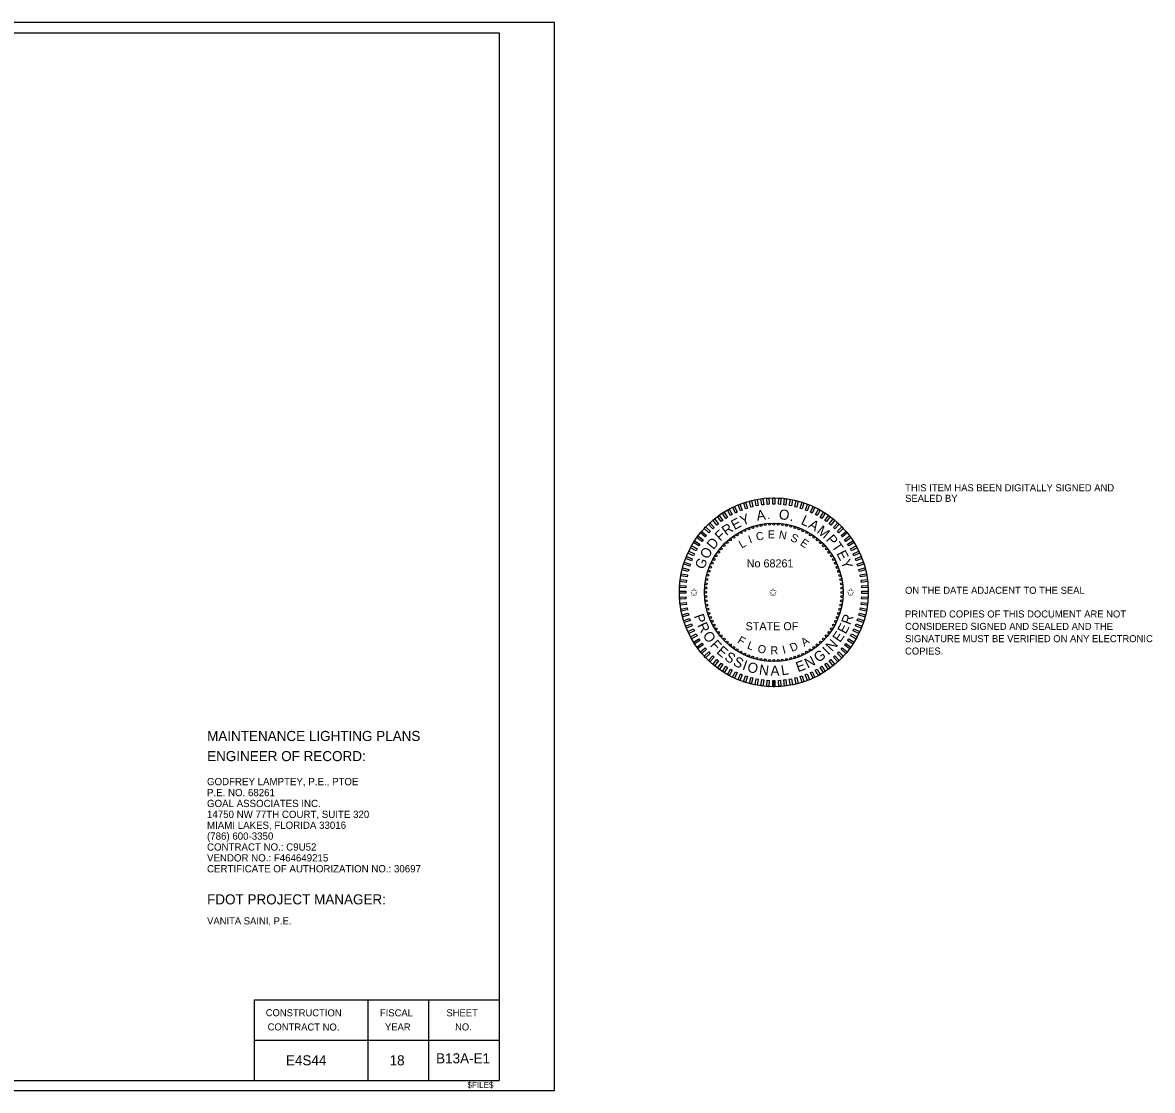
# Model space of a CAD drawing. Extents: x -828 to -798, y -2199 to -1895.
# Drawn here: x -809.01 to -797.79, y -2199.12 to -2188.52 of the extents above; entities that cross this region are included whole.
import ezdxf

# ---------------------------------------------------------------- set-up
doc = ezdxf.new("R2010")
doc.units = 0
for name, color, linetype in [('ActivePointCell_dp', 7, 'Continuous'), ('Logo_dp', 7, 'Continuous'), ('NonPlottingEle_dp', 7, 'Continuous'), ('PlotBorder_dp', 7, 'Continuous'), ('SheetBorder_dp', 7, 'Continuous'), ('SheetLines_dp', 7, 'Continuous'), ('TextLabel', 7, 'Continuous'), ('TextMinor', 7, 'Continuous'), ('TextMisc', 7, 'Continuous'), ('TextNotes', 7, 'Continuous')]:
    doc.layers.add(name, color=color, linetype=linetype)

msp = doc.modelspace()

# ---------------------------------------------------------------- linework, layer by layer
at = {"layer": 'ActivePointCell_dp'}
msp.add_line((-804.277, -2188.624), (-804.277, -2188.624), dxfattribs=at)
at = {"layer": 'Logo_dp'}
for p, q in [((-801.56, -2195.117), (-801.56, -2195.054)), ((-801.55, -2195.117), (-801.55, -2195.054)), ((-801.54, -2195.117), (-801.54, -2195.054))]:
    msp.add_line(p, q, dxfattribs=at)
for points in [[(-801.914, -2193.383), (-801.932, -2193.392), (-801.958, -2193.335), (-801.94, -2193.327)], [(-801.863, -2193.362), (-801.882, -2193.369), (-801.905, -2193.311), (-801.886, -2193.304)], [(-801.811, -2193.344), (-801.83, -2193.35), (-801.849, -2193.291), (-801.83, -2193.285)], [(-801.758, -2193.329), (-801.777, -2193.334), (-801.793, -2193.274), (-801.773, -2193.269)], [(-801.704, -2193.318), (-801.724, -2193.322), (-801.736, -2193.26), (-801.716, -2193.257)], [(-801.65, -2193.31), (-801.67, -2193.312), (-801.678, -2193.251), (-801.658, -2193.248)], [(-801.595, -2193.305), (-801.615, -2193.307), (-801.619, -2193.244), (-801.599, -2193.243)], [(-801.54, -2193.304), (-801.56, -2193.304), (-801.56, -2193.242), (-801.54, -2193.242)], [(-801.485, -2193.307), (-801.505, -2193.305), (-801.501, -2193.243), (-801.481, -2193.244)], [(-801.43, -2193.313), (-801.45, -2193.31), (-801.443, -2193.248), (-801.423, -2193.251)], [(-801.376, -2193.322), (-801.396, -2193.318), (-801.384, -2193.257), (-801.364, -2193.26)], [(-801.323, -2193.334), (-801.342, -2193.329), (-801.327, -2193.269), (-801.307, -2193.274)], [(-801.27, -2193.35), (-801.289, -2193.344), (-801.27, -2193.285), (-801.251, -2193.291)], [(-801.219, -2193.37), (-801.237, -2193.362), (-801.214, -2193.304), (-801.196, -2193.311)], [(-801.168, -2193.392), (-801.187, -2193.383), (-801.16, -2193.327), (-801.142, -2193.335)], [(-802.1, -2193.499), (-802.116, -2193.512), (-802.155, -2193.463), (-802.14, -2193.451)], [(-802.056, -2193.465), (-802.073, -2193.477), (-802.109, -2193.427), (-802.093, -2193.415)], [(-802.01, -2193.435), (-802.027, -2193.446), (-802.061, -2193.393), (-802.044, -2193.382)], [(-801.963, -2193.408), (-801.98, -2193.417), (-802.011, -2193.363), (-801.993, -2193.353)], [(-801.12, -2193.417), (-801.137, -2193.408), (-801.107, -2193.353), (-801.09, -2193.363)], [(-801.073, -2193.446), (-801.09, -2193.435), (-801.056, -2193.382), (-801.039, -2193.393)], [(-801.028, -2193.477), (-801.044, -2193.466), (-801.007, -2193.415), (-800.991, -2193.427)], [(-800.985, -2193.512), (-801, -2193.499), (-800.96, -2193.451), (-800.945, -2193.464)], [(-802.181, -2193.573), (-802.195, -2193.588), (-802.24, -2193.545), (-802.227, -2193.53)], [(-802.142, -2193.535), (-802.156, -2193.548), (-802.199, -2193.503), (-802.184, -2193.489)], [(-800.944, -2193.548), (-800.958, -2193.535), (-800.916, -2193.489), (-800.901, -2193.503)], [(-800.905, -2193.588), (-800.919, -2193.573), (-800.874, -2193.53), (-800.86, -2193.545)], [(-802.284, -2193.702), (-802.294, -2193.719), (-802.347, -2193.685), (-802.336, -2193.668)], [(-802.252, -2193.657), (-802.264, -2193.673), (-802.314, -2193.636), (-802.303, -2193.62)], [(-802.218, -2193.614), (-802.231, -2193.629), (-802.279, -2193.59), (-802.266, -2193.574)], [(-800.869, -2193.629), (-800.882, -2193.614), (-800.834, -2193.574), (-800.821, -2193.59)], [(-800.836, -2193.673), (-800.848, -2193.657), (-800.798, -2193.62), (-800.786, -2193.637)], [(-800.806, -2193.719), (-800.817, -2193.702), (-800.764, -2193.669), (-800.753, -2193.686)], [(-802.338, -2193.798), (-802.346, -2193.816), (-802.403, -2193.789), (-802.394, -2193.771)], [(-802.312, -2193.749), (-802.322, -2193.767), (-802.376, -2193.737), (-802.367, -2193.719)], [(-800.778, -2193.767), (-800.788, -2193.749), (-800.733, -2193.719), (-800.724, -2193.737)], [(-800.754, -2193.816), (-800.763, -2193.798), (-800.706, -2193.771), (-800.698, -2193.789)], [(-802.379, -2193.899), (-802.385, -2193.918), (-802.445, -2193.899), (-802.439, -2193.88)], [(-802.36, -2193.848), (-802.367, -2193.867), (-802.425, -2193.844), (-802.418, -2193.825)], [(-800.733, -2193.867), (-800.74, -2193.848), (-800.682, -2193.825), (-800.675, -2193.844)], [(-800.715, -2193.919), (-800.721, -2193.899), (-800.662, -2193.88), (-800.655, -2193.899)], [(-802.408, -2194.005), (-802.412, -2194.025), (-802.473, -2194.014), (-802.469, -2193.994)], [(-802.395, -2193.952), (-802.4, -2193.971), (-802.461, -2193.956), (-802.456, -2193.936)], [(-800.7, -2193.972), (-800.705, -2193.952), (-800.645, -2193.937), (-800.64, -2193.956)], [(-800.689, -2194.025), (-800.693, -2194.006), (-800.631, -2193.994), (-800.627, -2194.014)], [(-802.423, -2194.114), (-802.424, -2194.134), (-802.486, -2194.13), (-802.485, -2194.11)], [(-802.417, -2194.06), (-802.42, -2194.08), (-802.481, -2194.072), (-802.479, -2194.052)], [(-800.681, -2194.08), (-800.683, -2194.06), (-800.621, -2194.052), (-800.619, -2194.072)], [(-800.676, -2194.135), (-800.677, -2194.114), (-800.615, -2194.111), (-800.614, -2194.131)], [(-802.425, -2194.169), (-802.425, -2194.189), (-802.488, -2194.189), (-802.488, -2194.169)], [(-802.424, -2194.224), (-802.423, -2194.244), (-802.485, -2194.248), (-802.486, -2194.228)], [(-800.678, -2194.244), (-800.676, -2194.224), (-800.614, -2194.228), (-800.615, -2194.248)], [(-800.675, -2194.19), (-800.675, -2194.169), (-800.613, -2194.169), (-800.613, -2194.19)], [(-802.42, -2194.279), (-802.417, -2194.299), (-802.479, -2194.307), (-802.482, -2194.287)], [(-802.412, -2194.333), (-802.408, -2194.353), (-802.469, -2194.365), (-802.473, -2194.345)], [(-800.693, -2194.353), (-800.689, -2194.334), (-800.627, -2194.345), (-800.631, -2194.365)], [(-800.683, -2194.299), (-800.681, -2194.279), (-800.619, -2194.287), (-800.621, -2194.307)], [(-802.4, -2194.387), (-802.395, -2194.407), (-802.456, -2194.422), (-802.461, -2194.403)], [(-802.386, -2194.44), (-802.379, -2194.459), (-802.439, -2194.479), (-802.445, -2194.459)], [(-800.721, -2194.459), (-800.715, -2194.44), (-800.655, -2194.46), (-800.662, -2194.479)], [(-800.705, -2194.407), (-800.7, -2194.387), (-800.64, -2194.403), (-800.645, -2194.422)], [(-802.367, -2194.492), (-802.36, -2194.511), (-802.418, -2194.534), (-802.426, -2194.515)], [(-802.346, -2194.543), (-802.338, -2194.561), (-802.394, -2194.588), (-802.403, -2194.569)], [(-800.763, -2194.561), (-800.754, -2194.543), (-800.698, -2194.569), (-800.706, -2194.588)], [(-800.74, -2194.511), (-800.733, -2194.492), (-800.675, -2194.515), (-800.682, -2194.534)], [(-802.322, -2194.592), (-802.312, -2194.61), (-802.367, -2194.64), (-802.377, -2194.622)], [(-802.294, -2194.64), (-802.284, -2194.657), (-802.336, -2194.69), (-802.347, -2194.673)], [(-802.264, -2194.685), (-802.252, -2194.702), (-802.303, -2194.738), (-802.315, -2194.722)], [(-800.848, -2194.702), (-800.836, -2194.686), (-800.786, -2194.722), (-800.798, -2194.739)], [(-800.817, -2194.657), (-800.806, -2194.64), (-800.753, -2194.673), (-800.764, -2194.69)], [(-800.788, -2194.61), (-800.779, -2194.592), (-800.724, -2194.622), (-800.734, -2194.64)], [(-802.231, -2194.729), (-802.218, -2194.745), (-802.266, -2194.785), (-802.279, -2194.769)], [(-802.195, -2194.771), (-802.181, -2194.786), (-802.227, -2194.828), (-802.241, -2194.814)], [(-800.919, -2194.786), (-800.905, -2194.771), (-800.86, -2194.814), (-800.874, -2194.829)], [(-800.882, -2194.745), (-800.87, -2194.729), (-800.821, -2194.769), (-800.834, -2194.785)], [(-802.157, -2194.81), (-802.142, -2194.824), (-802.185, -2194.87), (-802.199, -2194.856)], [(-802.116, -2194.847), (-802.1, -2194.86), (-802.14, -2194.908), (-802.156, -2194.895)], [(-802.073, -2194.881), (-802.056, -2194.893), (-802.093, -2194.944), (-802.109, -2194.932)], [(-801.044, -2194.893), (-801.028, -2194.881), (-800.991, -2194.932), (-801.007, -2194.944)], [(-801, -2194.86), (-800.985, -2194.847), (-800.945, -2194.895), (-800.96, -2194.908)], [(-800.959, -2194.824), (-800.944, -2194.81), (-800.901, -2194.856), (-800.916, -2194.87)], [(-802.028, -2194.913), (-802.011, -2194.924), (-802.044, -2194.976), (-802.061, -2194.965)], [(-801.981, -2194.941), (-801.963, -2194.951), (-801.993, -2195.006), (-802.011, -2194.996)], [(-801.932, -2194.967), (-801.914, -2194.975), (-801.94, -2195.032), (-801.959, -2195.023)], [(-801.882, -2194.989), (-801.863, -2194.997), (-801.886, -2195.055), (-801.905, -2195.047)], [(-801.83, -2195.008), (-801.811, -2195.015), (-801.83, -2195.074), (-801.85, -2195.068)], [(-801.289, -2195.015), (-801.27, -2195.008), (-801.251, -2195.068), (-801.27, -2195.074)], [(-801.238, -2194.997), (-801.219, -2194.989), (-801.196, -2195.047), (-801.215, -2195.055)], [(-801.187, -2194.975), (-801.169, -2194.967), (-801.142, -2195.023), (-801.16, -2195.032)], [(-801.138, -2194.951), (-801.12, -2194.941), (-801.09, -2194.996), (-801.107, -2195.006)], [(-801.09, -2194.924), (-801.073, -2194.913), (-801.039, -2194.966), (-801.056, -2194.976)], [(-801.778, -2195.024), (-801.758, -2195.029), (-801.774, -2195.09), (-801.793, -2195.085)], [(-801.724, -2195.037), (-801.704, -2195.041), (-801.716, -2195.102), (-801.736, -2195.098)], [(-801.67, -2195.046), (-801.65, -2195.049), (-801.658, -2195.111), (-801.678, -2195.108)], [(-801.615, -2195.052), (-801.595, -2195.053), (-801.599, -2195.116), (-801.619, -2195.114)], [(-801.56, -2195.054), (-801.54, -2195.054), (-801.54, -2195.117), (-801.56, -2195.117)], [(-801.505, -2195.053), (-801.485, -2195.052), (-801.481, -2195.114), (-801.501, -2195.116)], [(-801.451, -2195.049), (-801.431, -2195.046), (-801.423, -2195.108), (-801.443, -2195.111)], [(-801.396, -2195.041), (-801.376, -2195.037), (-801.365, -2195.098), (-801.385, -2195.102)], [(-801.342, -2195.029), (-801.323, -2195.024), (-801.307, -2195.085), (-801.327, -2195.09)]]:
    msp.add_lwpolyline(points, close=True, dxfattribs=at)
for centre in [(-801.838, -2193.566), (-801.799, -2193.549), (-801.759, -2193.535), (-801.718, -2193.523), (-801.677, -2193.514), (-801.635, -2193.507), (-801.592, -2193.503), (-801.55, -2193.502), (-801.507, -2193.503), (-801.465, -2193.507), (-801.423, -2193.514), (-801.381, -2193.523), (-801.34, -2193.535), (-801.3, -2193.55), (-801.261, -2193.567), (-802.014, -2193.685), (-801.982, -2193.657), (-801.948, -2193.631), (-801.913, -2193.607), (-801.876, -2193.585), (-801.223, -2193.586), (-801.187, -2193.608), (-801.152, -2193.632), (-801.118, -2193.658), (-801.086, -2193.686), (-802.098, -2193.781), (-802.072, -2193.747), (-802.044, -2193.715), (-801.056, -2193.716), (-801.028, -2193.748), (-801.002, -2193.782), (-802.163, -2193.89), (-802.144, -2193.853), (-802.122, -2193.816), (-800.978, -2193.817), (-800.956, -2193.853), (-800.937, -2193.891), (-802.206, -2194.01), (-802.194, -2193.969), (-802.18, -2193.929), (-800.92, -2193.931), (-800.906, -2193.971), (-800.894, -2194.011), (-802.222, -2194.094), (-802.216, -2194.052), (-800.885, -2194.053), (-800.878, -2194.095), (-802.228, -2194.179), (-802.226, -2194.136), (-802.226, -2194.221), (-800.874, -2194.137), (-800.874, -2194.222), (-800.873, -2194.18), (-802.222, -2194.264), (-802.216, -2194.306), (-802.206, -2194.347), (-800.894, -2194.348), (-800.885, -2194.307), (-800.878, -2194.265), (-802.195, -2194.388), (-802.18, -2194.428), (-802.163, -2194.467), (-800.937, -2194.468), (-800.92, -2194.429), (-800.906, -2194.389), (-802.144, -2194.505), (-802.122, -2194.542), (-802.099, -2194.577), (-801.002, -2194.578), (-800.978, -2194.543), (-800.957, -2194.506), (-802.073, -2194.611), (-802.044, -2194.643), (-802.014, -2194.673), (-801.087, -2194.674), (-801.057, -2194.644), (-801.029, -2194.612), (-801.982, -2194.701), (-801.949, -2194.727), (-801.914, -2194.751), (-801.877, -2194.773), (-801.839, -2194.792), (-801.262, -2194.793), (-801.224, -2194.773), (-801.188, -2194.752), (-801.152, -2194.728), (-801.119, -2194.702), (-801.8, -2194.809), (-801.76, -2194.824), (-801.719, -2194.835), (-801.678, -2194.845), (-801.636, -2194.851), (-801.593, -2194.855), (-801.55, -2194.857), (-801.508, -2194.856), (-801.466, -2194.852), (-801.424, -2194.845), (-801.382, -2194.836), (-801.341, -2194.824), (-801.301, -2194.809)]:
    msp.add_circle(centre, 0.01, dxfattribs=at)
at = {"layer": 'NonPlottingEle_dp'}
for radius in [0.938, 0.688]:
    msp.add_circle((-801.55, -2194.179), radius, dxfattribs=at)
at = {"layer": 'PlotBorder_dp'}
msp.add_lwpolyline([(-820.227, -2199.124), (-803.727, -2199.124), (-803.727, -2188.524), (-820.227, -2188.524)], close=True, dxfattribs=at)
at = {"layer": 'SheetBorder_dp'}
for p, q in [((-819.677, -2188.624), (-804.277, -2188.624)), ((-804.277, -2188.624), (-804.277, -2199.024)), ((-819.677, -2199.024), (-804.277, -2199.024))]:
    msp.add_line(p, q, dxfattribs=at)
at = {"layer": 'SheetLines_dp'}
for p, q in [((-806.708, -2198.224), (-804.277, -2198.224)), ((-806.708, -2199.024), (-806.708, -2198.224)), ((-805.577, -2199.024), (-805.577, -2198.224)), ((-804.977, -2199.024), (-804.977, -2198.224)), ((-806.708, -2198.624), (-804.277, -2198.624))]:
    msp.add_line(p, q, dxfattribs=at)

# ---------------------------------------------------------------- texts
at = {"layer": 'Logo_dp'}
for s, height, rotation, p in [('E', 0.1, 28.1055, (-801.941, -2193.563)), ('Y', 0.1, 21.0633, (-801.862, -2193.52)), ('A', 0.1, 8.8088, (-801.715, -2193.469)), ('.', 0.1, 1.0418, (-801.618, -2193.453)), ('O', 0.1, 352.1877, (-801.505, -2193.451)), ('L', 0.1, 334.6727, (-801.288, -2193.499)), ('F', 0.1, 42.3772, (-802.081, -2193.678)), ('R', 0.1, 35.9269, (-802.021, -2193.622)), ('E', 0.08, 0.4186, (-801.61, -2193.644)), ('.', 0.1, 343.5268, (-801.396, -2193.466)), ('A', 0.1, 328.4096, (-801.215, -2193.531)), ('M', 0.1, 320.6426, (-801.131, -2193.583)), ('D', 0.1, 50.8569, (-802.149, -2193.762)), ('L', 0.08, 30.4021, (-801.869, -2193.746)), ('I', 0.08, 20.0117, (-801.786, -2193.695)), ('C', 0.08, 12.2025, (-801.718, -2193.668)), ('N', 0.08, 349.2914, (-801.505, -2193.643)), ('S', 0.08, 337.0221, (-801.392, -2193.665)), ('E', 0.08, 325.8663, (-801.296, -2193.705)), ('P', 0.1, 311.1966, (-801.038, -2193.659)), ('T', 0.1, 304.4563, (-800.981, -2193.723)), ('O', 0.1, 59.5178, (-802.205, -2193.857)), ('E', 0.1, 297.6315, (-800.931, -2193.794)), ('G', 0.1, 68.0518, (-802.245, -2193.958)), ('Y', 0.1, 290.5893, (-800.888, -2193.873)), ('P', 0.1, 289.4055, (-802.345, -2194.414)), ('R', 0.1, 69.5134, (-800.79, -2194.509)), ('R', 0.1, 296.1458, (-802.312, -2194.506)), ('O', 0.1, 303.9671, (-802.26, -2194.606)), ('E', 0.1, 55.4289, (-800.893, -2194.684)), ('E', 0.1, 62.4712, (-800.836, -2194.6)), ('F', 0.1, 312.628, (-802.188, -2194.708)), ('F', 0.08, 328.7241, (-801.918, -2194.676)), ('L', 0.08, 339.2916, (-801.821, -2194.735)), ('D', 0.08, 22.0128, (-801.372, -2194.771)), ('A', 0.08, 34.4992, (-801.248, -2194.719)), ('N', 0.1, 47.1788, (-800.972, -2194.773)), ('E', 0.1, 319.0783, (-802.125, -2194.777)), ('S', 0.1, 326.1206, (-802.047, -2194.843)), ('O', 0.08, 349.6821, (-801.716, -2194.775)), ('R', 0.08, 2.3398, (-801.582, -2194.797)), ('I', 0.08, 14.2037, (-801.454, -2194.79)), ('G', 0.1, 35.1115, (-801.109, -2194.881)), ('I', 0.1, 43.6456, (-801.01, -2194.808)), ('S', 0.1, 333.193, (-801.962, -2194.899)), ('I', 0.1, 340.2654, (-801.87, -2194.944)), ('O', 0.1, 343.7986, (-801.822, -2194.962)), ('N', 0.1, 352.4595, (-801.701, -2194.994)), ('A', 0.1, 0.7097, (-801.583, -2195.007)), ('L', 0.1, 8.4767, (-801.471, -2195.004)), ('E', 0.1, 19.8191, (-801.31, -2194.972)), ('N', 0.1, 26.8614, (-801.214, -2194.937))]:
    msp.add_text(s, height=height, rotation=rotation, dxfattribs=at).set_placement(p)
for s, p in [('No 68261', (-801.819, -2193.932)), ('✩', (-802.385, -2194.217)), ('✩', (-801.6, -2194.217)), ('✩', (-800.829, -2194.217)), ('STATE OF', (-801.83, -2194.556))]:
    msp.add_text(s, height=0.08, dxfattribs=at).set_placement(p)
at = {"layer": 'TextLabel'}
for s, height, p in [('MAINTENANCE LIGHTING PLANS', 0.1, (-807.177, -2195.655)), ('ENGINEER OF RECORD:', 0.1, (-807.177, -2195.855)), ('GODFREY LAMPTEY, P.E., PTOE', 0.07202, (-807.178, -2196.094)), ('P.E. NO. 68261', 0.07202, (-807.178, -2196.203)), ('GOAL ASSOCIATES INC. ', 0.07202, (-807.178, -2196.311)), ('14750 NW 77TH COURT, SUITE 320', 0.07202, (-807.178, -2196.419)), ('MIAMI LAKES, FLORIDA 33016', 0.07202, (-807.178, -2196.527)), ('(786) 600-3350', 0.07202, (-807.178, -2196.635)), ('CONTRACT NO.: C9U52', 0.07202, (-807.178, -2196.743)), ('VENDOR NO.: F464649215', 0.07202, (-807.178, -2196.851)), ('CERTIFICATE OF AUTHORIZATION NO.: 30697', 0.07202, (-807.178, -2196.959)), ('E4S44', 0.1, (-806.394, -2198.875)), ('18', 0.1, (-805.365, -2198.875)), ('B13A-E1', 0.1, (-804.903, -2198.855))]:
    msp.add_text(s, height=height, dxfattribs=at).set_placement(p)
at = {"layer": 'TextMinor'}
msp.add_text('$FILE$', height=0.06, dxfattribs=at).set_placement((-804.592, -2199.099))
at = {"layer": 'TextMisc'}
for s, p in [('THIS ITEM HAS BEEN DIGITALLY SIGNED AND ', (-800.246, -2193.176)), ('SEALED BY', (-800.246, -2193.281)), ('ON THE DATE ADJACENT TO THE SEAL', (-800.247, -2194.194)), ('PRINTED COPIES OF THIS DOCUMENT ARE NOT ', (-800.247, -2194.429)), ('CONSIDERED SIGNED AND SEALED AND THE ', (-800.247, -2194.552)), ('SIGNATURE MUST BE VERIFIED ON ANY ELECTRONIC ', (-800.247, -2194.674)), ('COPIES.', (-800.247, -2194.797))]:
    msp.add_text(s, height=0.07, dxfattribs=at).set_placement(p)
at = {"layer": 'TextNotes'}
for s, height, p in [('FDOT PROJECT MANAGER:', 0.1, (-807.177, -2197.277)), ('VANITA SAINI, P.E.', 0.07, (-807.177, -2197.476))]:
    msp.add_text(s, height=height, dxfattribs=at).set_placement(p)
for s, p in [('CONSTRUCTION', (-806.595, -2198.387)), ('FISCAL', (-805.461, -2198.388)), ('SHEET', (-804.801, -2198.388)), ('CONTRACT NO.', (-806.576, -2198.528)), ('YEAR', (-805.411, -2198.528)), ('NO.', (-804.715, -2198.528))]:
    msp.add_text(s, height=0.07, rotation=359.8607, dxfattribs=at).set_placement(p)

doc.saveas('drawing.dxf')
